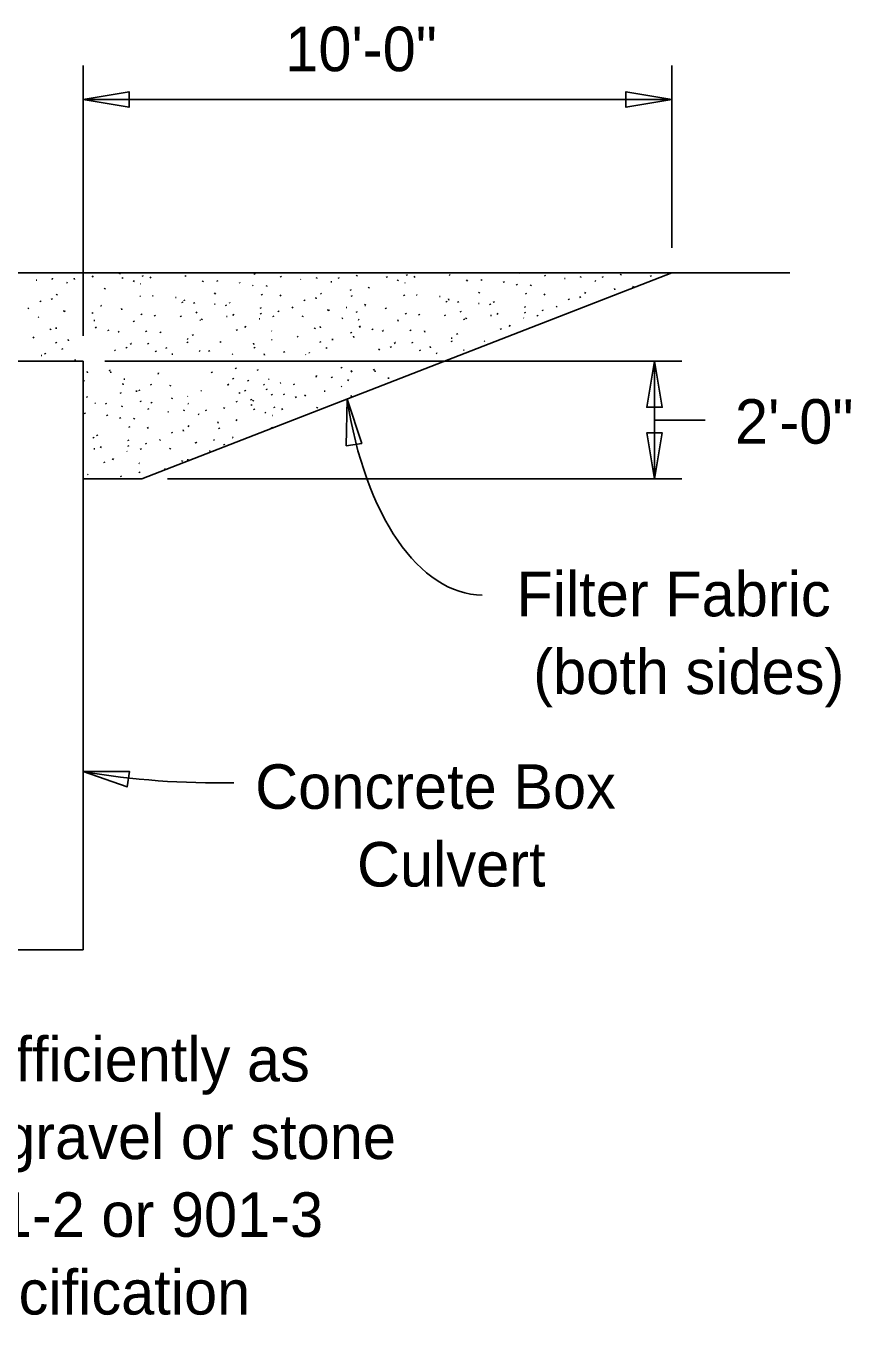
# Model space of a CAD drawing. Extents: x 1.4 to 54.1, y -0.5 to 22.6.
# Drawn here: x 28.703 to 31.505, y 6.775 to 11.198 of the extents above; entities that cross this region are included whole.
import ezdxf

# ---------------------------------------------------------------- set-up
doc = ezdxf.new("R2010")
doc.units = 0
for name, color, linetype in [('AdhocPoint_dp', 7, 'Continuous'), ('Border', 7, 'Continuous'), ('Leader', 7, 'Continuous'), ('PlotBorder_dp', 7, 'Continuous'), ('WallConc', 7, 'Continuous')]:
    doc.layers.add(name, color=color, linetype=linetype)

msp = doc.modelspace()

# ---------------------------------------------------------------- linework, layer by layer
at = {"layer": 'Border'}
for p, q in [((29.0233, 10.3597), (29.0208, 10.3559)), ((29.1005, 10.348), (29.0985, 10.3514)), ((29.2463, 10.3512), (29.2437, 10.3474)), ((29.4801, 10.3578), (29.4782, 10.3545)), ((29.8279, 10.3526), (29.8253, 10.3486)), ((29.9184, 10.3597), (29.9179, 10.3589)), ((29.9976, 10.351), (29.9956, 10.3543)), ((30.1433, 10.3542), (30.1407, 10.3504)), ((30.3766, 10.3597), (30.3753, 10.3575)), ((30.4667, 10.3484), (30.4648, 10.3516)), ((30.7249, 10.3556), (30.7223, 10.3516)), ((30.8263, 10.3472), (30.8244, 10.3505)), ((28.7399, 10.3352), (28.738, 10.3346)), ((28.7935, 10.3417), (28.7922, 10.3378)), ((28.8445, 10.326), (28.8412, 10.3267)), ((28.8681, 10.3378), (28.8668, 10.3417)), ((28.9308, 10.3496), (28.9282, 10.3456)), ((28.972, 10.3084), (28.9694, 10.3045)), ((29.0322, 10.3412), (29.0302, 10.3445)), ((29.0705, 10.3337), (29.0678, 10.3298)), ((29.0934, 10.3225), (29.0923, 10.3228)), ((29.1267, 10.3415), (29.1248, 10.346)), ((29.3051, 10.333), (29.3025, 10.329)), ((29.354, 10.3309), (29.3521, 10.3343)), ((29.4298, 10.3245), (29.4279, 10.3277)), ((29.4742, 10.3153), (29.4723, 10.3185)), ((29.5213, 10.3166), (29.5194, 10.3133)), ((29.5697, 10.3454), (29.5677, 10.3486)), ((29.6369, 10.3382), (29.635, 10.3376)), ((29.6906, 10.3447), (29.6892, 10.3408)), ((29.7416, 10.329), (29.7383, 10.3297)), ((29.7651, 10.3408), (29.7639, 10.3447)), ((29.869, 10.3114), (29.8664, 10.3074)), ((29.9292, 10.3442), (29.9273, 10.3475)), ((29.9675, 10.3367), (29.9649, 10.3328)), ((29.9905, 10.3255), (29.9894, 10.3258)), ((30.0238, 10.3444), (30.0218, 10.349)), ((30.2021, 10.336), (30.1995, 10.332)), ((30.2511, 10.3339), (30.2491, 10.3373)), ((30.3269, 10.3275), (30.3249, 10.3307)), ((30.3712, 10.3183), (30.3694, 10.3215)), ((30.4184, 10.3196), (30.4164, 10.3163)), ((30.534, 10.3412), (30.5321, 10.3405)), ((30.5876, 10.3477), (30.5863, 10.3438)), ((30.6386, 10.332), (30.6353, 10.3326)), ((30.6622, 10.3437), (30.6609, 10.3477)), ((30.7034, 10.3026), (30.7021, 10.3066)), ((30.7661, 10.3144), (30.7635, 10.3104)), ((28.7531, 10.262), (28.7511, 10.2652)), ((28.7916, 10.2692), (28.7903, 10.2731)), ((28.8092, 10.2881), (28.8066, 10.2842)), ((29.0917, 10.2791), (29.0897, 10.2823)), ((29.1346, 10.2814), (29.1326, 10.282)), ((29.2129, 10.2761), (29.2104, 10.2762)), ((29.2418, 10.2644), (29.2404, 10.2683)), ((29.3462, 10.2918), (29.3436, 10.2879)), ((29.505, 10.2845), (29.503, 10.2878)), ((29.505, 10.2845), (29.503, 10.2878)), ((29.5684, 10.2813), (29.5658, 10.2853)), ((29.6502, 10.2649), (29.6481, 10.2682)), ((29.6886, 10.2722), (29.6873, 10.2761)), ((29.7063, 10.2911), (29.7037, 10.2872)), ((29.8063, 10.2996), (29.805, 10.3036)), ((29.8102, 10.2801), (29.8083, 10.2833)), ((29.9888, 10.282), (29.9868, 10.2853)), ((30.0316, 10.2844), (30.0296, 10.285)), ((30.11, 10.2791), (30.1074, 10.2792)), ((30.1322, 10.2608), (30.1302, 10.2641)), ((30.1388, 10.2673), (30.1375, 10.2713)), ((30.1721, 10.2588), (30.1701, 10.2621)), ((30.2432, 10.2948), (30.2406, 10.2909)), ((30.2929, 10.2595), (30.291, 10.2628)), ((30.2929, 10.2595), (30.291, 10.2628)), ((30.402, 10.2875), (30.4001, 10.2908)), ((30.402, 10.2875), (30.4001, 10.2908)), ((30.4654, 10.2843), (30.4628, 10.2883)), ((30.5472, 10.2679), (30.5452, 10.2712)), ((30.5857, 10.2752), (30.5844, 10.2791)), ((30.6033, 10.2941), (30.6007, 10.2902)), ((30.7059, 10.2855), (30.7054, 10.2863)), ((28.7124, 10.2372), (28.7099, 10.2411)), ((28.8327, 10.228), (28.8314, 10.2319)), ((28.8353, 10.228), (28.8334, 10.2312)), ((28.93, 10.2221), (28.9282, 10.2254)), ((28.9596, 10.2503), (28.9569, 10.2477)), ((28.9589, 10.2457), (28.957, 10.2464)), ((29.0289, 10.2345), (29.0276, 10.2384)), ((29.0967, 10.217), (29.0947, 10.2203)), ((29.2352, 10.2578), (29.2332, 10.2611)), ((29.275, 10.2559), (29.2731, 10.2591)), ((29.2829, 10.2232), (29.2815, 10.2272)), ((29.3456, 10.2532), (29.3429, 10.2533)), ((29.3835, 10.248), (29.3815, 10.2512)), ((29.3958, 10.2565), (29.394, 10.2598)), ((29.3958, 10.2565), (29.394, 10.2598)), ((29.409, 10.2199), (29.4057, 10.2154)), ((29.5011, 10.2389), (29.4998, 10.2428)), ((29.5017, 10.2199), (29.4998, 10.2232)), ((29.5618, 10.2278), (29.5598, 10.231)), ((29.6095, 10.2402), (29.607, 10.2441)), ((29.7298, 10.231), (29.7285, 10.2349)), ((29.7324, 10.231), (29.7304, 10.2342)), ((29.7932, 10.2421), (29.7899, 10.2428)), ((29.8271, 10.2251), (29.8252, 10.2283)), ((29.8566, 10.2533), (29.854, 10.2506)), ((29.856, 10.2487), (29.854, 10.2493)), ((29.9259, 10.2375), (29.9246, 10.2414)), ((29.9937, 10.22), (29.9917, 10.2233)), ((30.039, 10.2161), (30.037, 10.2194)), ((30.1799, 10.2262), (30.1786, 10.2302)), ((30.2426, 10.2562), (30.24, 10.2562)), ((30.2805, 10.251), (30.2785, 10.2542)), ((30.306, 10.2229), (30.3027, 10.2183)), ((30.3981, 10.2419), (30.3968, 10.2458)), ((30.3987, 10.2229), (30.3968, 10.2262)), ((30.4588, 10.2307), (30.4569, 10.234)), ((30.5066, 10.2432), (30.504, 10.2471)), ((28.7465, 10.211), (28.7446, 10.2078)), ((28.8059, 10.1699), (28.8054, 10.1744)), ((28.9373, 10.1979), (28.9341, 10.1985)), ((28.9412, 10.1718), (28.9393, 10.1764)), ((29.0701, 10.1934), (29.0688, 10.1973)), ((29.1419, 10.2132), (29.1399, 10.2164)), ((29.2299, 10.2108), (29.228, 10.214)), ((29.2299, 10.2108), (29.228, 10.214)), ((29.2953, 10.1977), (29.2933, 10.2009)), ((29.3018, 10.2043), (29.2992, 10.2003)), ((29.3867, 10.2121), (29.3841, 10.2121)), ((29.4501, 10.1788), (29.4469, 10.1742)), ((29.4972, 10.2035), (29.4952, 10.2042)), ((29.5442, 10.2102), (29.5422, 10.2134)), ((29.5442, 10.2102), (29.5422, 10.2134)), ((29.6435, 10.214), (29.6417, 10.2107)), ((29.703, 10.1728), (29.7024, 10.1774)), ((29.7788, 10.2055), (29.7762, 10.2054)), ((29.8343, 10.2009), (29.8311, 10.2015)), ((29.8383, 10.1748), (29.8363, 10.1794)), ((29.9671, 10.1963), (29.9658, 10.2002)), ((30.127, 10.2138), (30.125, 10.217)), ((30.127, 10.2138), (30.125, 10.217)), ((30.1923, 10.2007), (30.1903, 10.2039)), ((30.1989, 10.2073), (30.1963, 10.2033)), ((30.2837, 10.2151), (30.2811, 10.2151)), ((30.3472, 10.1817), (30.3439, 10.1772)), ((30.3942, 10.2065), (30.3923, 10.2072)), ((30.4412, 10.2131), (30.4392, 10.2164)), ((30.4412, 10.2131), (30.4392, 10.2164)), ((28.7301, 10.1424), (28.7276, 10.1385)), ((28.7877, 10.1698), (28.7857, 10.1666)), ((28.8471, 10.1287), (28.8465, 10.1333)), ((28.9838, 10.1632), (28.9818, 10.1665)), ((29.0184, 10.16), (29.0158, 10.1587)), ((29.0198, 10.1614), (29.019, 10.1609)), ((29.1126, 10.16), (29.1106, 10.1633)), ((29.1606, 10.156), (29.1593, 10.1599)), ((29.2535, 10.135), (29.2502, 10.1357)), ((29.2711, 10.1474), (29.2691, 10.1506)), ((29.4201, 10.1644), (29.4181, 10.1677)), ((29.5383, 10.1624), (29.5364, 10.1631)), ((29.5397, 10.131), (29.5371, 10.1336)), ((29.6272, 10.1454), (29.6246, 10.1415)), ((29.6847, 10.1728), (29.6828, 10.1696)), ((29.7442, 10.1317), (29.7435, 10.1362)), ((29.8082, 10.1552), (29.8062, 10.1584)), ((29.8162, 10.1408), (29.8148, 10.1447)), ((29.8808, 10.1662), (29.8789, 10.1695)), ((29.9155, 10.163), (29.9129, 10.1616)), ((29.9168, 10.1644), (29.916, 10.1639)), ((30.0096, 10.163), (30.0076, 10.1662)), ((30.0576, 10.159), (30.0563, 10.1629)), ((30.1505, 10.138), (30.1472, 10.1386)), ((30.1498, 10.1255), (30.1479, 10.1289)), ((30.1682, 10.1504), (30.1662, 10.1536)), ((30.2616, 10.1262), (30.2596, 10.1295)), ((30.3172, 10.1674), (30.3151, 10.1707)), ((28.7693, 10.0836), (28.7674, 10.0869)), ((28.8066, 10.1209), (28.8046, 10.1241)), ((28.8275, 10.0999), (28.8256, 10.1032)), ((29.0067, 10.0985), (29.004, 10.0946)), ((29.0458, 10.1037), (29.0438, 10.107)), ((29.0596, 10.1188), (29.0569, 10.1175)), ((29.061, 10.1202), (29.0601, 10.1198)), ((29.1191, 10.1182), (29.1171, 10.1215)), ((29.1452, 10.0921), (29.1433, 10.0954)), ((29.1804, 10.1025), (29.179, 10.1064)), ((29.2528, 10.1225), (29.2508, 10.1259)), ((29.2946, 10.0939), (29.2914, 10.0945)), ((29.326, 10.0926), (29.324, 10.0958)), ((29.3646, 10.1232), (29.3625, 10.1265)), ((29.4057, 10.0821), (29.4037, 10.0853)), ((29.4769, 10.1167), (29.4756, 10.1206)), ((29.4802, 10.1043), (29.4782, 10.1075)), ((29.5129, 10.0807), (29.5116, 10.0846)), ((29.5809, 10.0899), (29.5783, 10.0925)), ((29.6664, 10.0866), (29.6645, 10.0899)), ((29.7037, 10.1239), (29.7017, 10.1271)), ((29.7246, 10.1029), (29.7226, 10.1062)), ((29.9037, 10.1015), (29.901, 10.0976)), ((29.9429, 10.1067), (29.9409, 10.11)), ((29.9566, 10.1218), (29.954, 10.1205)), ((29.958, 10.1232), (29.9572, 10.1228)), ((30.0161, 10.1212), (30.0142, 10.1245)), ((30.0422, 10.0951), (30.0403, 10.0984)), ((30.0774, 10.1055), (30.0761, 10.1093)), ((30.0991, 10.0865), (30.0958, 10.0872)), ((30.1916, 10.0968), (30.1884, 10.0975)), ((30.222, 10.0973), (30.2211, 10.0988)), ((28.7569, 10.079), (28.755, 10.0797)), ((28.8714, 10.0613), (28.8695, 10.0659)), ((29.202, 10.0836), (29.1988, 10.0842)), ((29.654, 10.082), (29.6521, 10.0827)), ((28.9126, 10.0201), (28.9106, 10.0248)), ((28.9884, 10.0267), (28.9863, 10.03)), ((28.9884, 10.0267), (28.9863, 10.03)), ((28.9916, 10.0207), (28.9903, 10.0248)), ((29.0393, 9.9993), (29.0354, 9.9993)), ((29.153, 10.0201), (29.1517, 10.0162)), ((29.3349, 10.0208), (29.3329, 10.024)), ((29.4076, 9.999), (29.4057, 10.0023)), ((29.4169, 10.0344), (29.4149, 10.0376)), ((29.4906, 10.0285), (29.4888, 10.0317)), ((29.5286, 9.9971), (29.5266, 10.0003)), ((29.69, 10.0107), (29.6881, 10.0061)), ((29.7429, 10.0036), (29.7411, 10.0068)), ((29.7429, 10.0036), (29.7411, 10.0068)), ((29.7756, 10.0362), (29.7737, 10.0395)), ((29.7985, 9.9977), (29.7959, 9.9936)), ((29.8096, 10.0231), (29.8077, 10.0277)), ((29.8854, 10.0297), (29.8834, 10.033)), ((29.8854, 10.0297), (29.8834, 10.033)), ((29.8886, 10.0237), (29.8873, 10.0277)), ((29.9364, 10.0022), (29.9324, 10.0022)), ((28.9015, 9.9947), (28.8988, 9.9907)), ((29.0256, 9.9502), (29.0236, 9.9535)), ((29.0327, 9.9796), (29.0315, 9.9836)), ((29.0805, 9.9581), (29.0766, 9.9581)), ((29.0889, 9.9587), (29.087, 9.962)), ((29.1281, 9.9783), (29.1269, 9.9823)), ((29.1942, 9.9789), (29.1928, 9.9751)), ((29.2994, 9.9575), (29.2974, 9.9607)), ((29.392, 9.9819), (29.388, 9.9779)), ((29.4293, 9.954), (29.4267, 9.95)), ((29.4488, 9.9578), (29.4469, 9.9611)), ((29.4587, 9.9925), (29.4567, 9.9958)), ((29.5135, 9.982), (29.5096, 9.9781)), ((29.5214, 9.9624), (29.5194, 9.9658)), ((29.5684, 9.986), (29.5665, 9.9853)), ((29.6141, 9.9794), (29.6123, 9.9827)), ((29.7194, 9.9578), (29.7155, 9.9578)), ((29.7757, 9.9722), (29.7736, 9.9755)), ((29.7757, 9.9722), (29.7736, 9.9755)), ((29.7757, 9.9722), (29.7736, 9.9755)), ((29.9295, 9.9835), (29.9285, 9.9866)), ((28.9113, 9.9366), (28.9093, 9.9398)), ((28.9387, 9.9156), (28.9367, 9.9189)), ((28.9759, 9.9136), (28.9739, 9.9169)), ((29.0301, 9.9078), (29.0282, 9.9045)), ((29.0935, 9.9215), (29.0915, 9.9248)), ((29.1301, 9.9176), (29.1281, 9.9208)), ((29.1993, 9.9359), (29.1981, 9.9319)), ((29.253, 9.9398), (29.2511, 9.9405)), ((29.2555, 9.915), (29.2523, 9.9156)), ((29.4194, 9.9206), (29.4181, 9.9245)), ((29.4685, 9.9278), (29.4665, 9.9311)), ((29.4704, 9.9128), (29.4678, 9.9088)), ((29.4763, 9.9278), (29.4737, 9.9239)), ((29.5391, 9.9448), (29.5371, 9.9481)), ((29.5391, 9.9448), (29.5371, 9.9481)), ((29.5802, 9.9455), (29.5783, 9.9487)), ((29.6202, 9.9356), (29.6189, 9.9395)), ((29.6521, 9.9454), (29.6496, 9.9415)), ((29.7575, 9.9167), (29.7567, 9.9166)), ((29.8083, 9.9396), (29.8063, 9.9428)), ((28.904, 9.8809), (28.902, 9.8842)), ((28.9798, 9.8745), (28.9778, 9.8777)), ((29.0242, 9.8653), (29.0223, 9.8685)), ((29.0713, 9.8666), (29.0694, 9.8633)), ((29.1197, 9.8954), (29.1177, 9.8986)), ((29.1869, 9.8882), (29.185, 9.8875)), ((29.2405, 9.8947), (29.2392, 9.8908)), ((29.2915, 9.879), (29.2883, 9.8796)), ((29.3151, 9.8907), (29.3139, 9.8947)), ((29.3778, 9.9026), (29.3752, 9.8986)), ((29.4792, 9.8942), (29.4773, 9.8975)), ((29.5175, 9.8867), (29.5148, 9.8828)), ((29.5405, 9.8755), (29.5393, 9.8758)), ((29.5475, 9.901), (29.5456, 9.9043)), ((29.5738, 9.8944), (29.5718, 9.899)), ((29.6933, 9.9042), (29.6907, 9.9004)), ((29.0549, 9.8345), (29.053, 9.8378)), ((29.0549, 9.8345), (29.053, 9.8378)), ((29.1184, 9.8313), (29.1158, 9.8353)), ((29.2386, 9.8222), (29.2373, 9.8261)), ((29.2562, 9.8411), (29.2536, 9.8372)), ((29.3563, 9.8496), (29.355, 9.8536)), ((29.3602, 9.83), (29.3583, 9.8333)), ((29.419, 9.8614), (29.4164, 9.8574)), ((29.5388, 9.832), (29.5367, 9.8353)), ((28.9334, 9.798), (28.9315, 9.8012)), ((28.9458, 9.8065), (28.944, 9.8097)), ((28.9458, 9.8065), (28.944, 9.8097)), ((29.051, 9.7889), (29.0497, 9.7928)), ((29.1117, 9.7777), (29.1098, 9.781)), ((29.1595, 9.7902), (29.1569, 9.7941)), ((29.2001, 9.8149), (29.1981, 9.8182)), ((29.2798, 9.781), (29.2785, 9.7849)), ((29.2824, 9.781), (29.2804, 9.7842)), ((29.3431, 9.7921), (29.3399, 9.7927)), ((29.3771, 9.7751), (29.3752, 9.7783)), ((29.4066, 9.8033), (29.404, 9.8006)), ((29.4059, 9.7986), (29.404, 9.7993)), ((28.9367, 9.7621), (28.9341, 9.7621)), ((28.9589, 9.7699), (28.9557, 9.7653)), ((29.0471, 9.7535), (29.0452, 9.7542)), ((29.0517, 9.7699), (29.0497, 9.7732)), ((29.0941, 9.7601), (29.0922, 9.7634)), ((29.0941, 9.7601), (29.0922, 9.7634)), ((29.1935, 9.764), (29.1916, 9.7607)), ((29.3288, 9.7555), (29.3262, 9.7554)), ((28.9701, 9.7144), (28.9681, 9.7177)), ((29.0001, 9.7287), (28.9969, 9.7242)), ((29.0883, 9.7124), (29.0863, 9.7131)), ((29.1772, 9.6953), (29.1746, 9.6914)), ((29.2347, 9.7228), (29.2328, 9.7196)), ((29.253, 9.7228), (29.2524, 9.7274)), ((28.9145, 9.6732), (28.9125, 9.6765)), ((29.0269, 9.6666), (29.0255, 9.6706)), ((29.0897, 9.681), (29.0871, 9.6836))]:
    msp.add_line(p, q, dxfattribs=at)
at = {"layer": 'Leader'}
msp.add_arc((29.356, 11.3951), 2.768, 260.4513, 271.09, dxfattribs=at)
msp.add_ellipse((30.2607, 10.2042), major_axis=(0.0083, 0.9392), ratio=0.517574, start_param=1.870693, end_param=3.141593, dxfattribs=at)
at = {"layer": 'PlotBorder_dp'}
for p, q in [((28.8968, 10.1458), (28.8968, 11.0644)), ((30.8968, 10.4447), (30.8968, 11.0644)), ((28.8968, 10.9489), (30.8968, 10.9489)), ((28.9712, 10.0597), (30.9309, 10.0597)), ((30.8374, 9.6597), (30.8374, 10.0597)), ((30.8374, 9.8597), (31.0094, 9.8597)), ((29.1833, 9.6597), (30.9309, 9.6597))]:
    msp.add_line(p, q, dxfattribs=at)
for points in [[(28.8968, 10.9489), (29.053, 10.9224), (29.053, 10.9753)], [(30.8968, 10.9489), (30.7406, 10.9753), (30.7406, 10.9224)], [(30.8374, 10.0597), (30.811, 9.9036), (30.8639, 9.9036)], [(29.7938, 9.9308), (29.791, 9.7724), (29.8433, 9.7803)], [(30.8374, 9.6597), (30.8639, 9.8159), (30.811, 9.8159)], [(28.8968, 8.6654), (29.0465, 8.6134), (29.0552, 8.6656)]]:
    msp.add_lwpolyline(points, close=True, dxfattribs=at)
at = {"layer": 'WallConc'}
for p, q in [((31.2968, 10.3597), (23.6968, 10.3597)), ((29.0968, 9.6597), (30.8968, 10.3597)), ((28.8968, 10.0597), (26.0968, 10.0597)), ((28.8968, 8.0597), (28.8968, 10.0597)), ((28.8968, 9.6597), (29.0968, 9.6597)), ((28.8968, 8.0597), (26.0968, 8.0597))]:
    msp.add_line(p, q, dxfattribs=at)

# ---------------------------------------------------------------- texts
at = {"layer": 'AdhocPoint_dp'}
for s, p in [('10\'-0"', (29.5836, 11.045)), ('Filter Fabric', (30.3686, 9.1931)), ('(both sides)', (30.4257, 8.9291)), ('Concrete Box', (29.4814, 8.5391)), ('Culvert', (29.8273, 8.2751)), ('Place coarse aggregate in 6 inch lifts and compact sufficiently as', (23.8791, 7.613)), ('to be firm and unyielding.  Provide coarse aggregate gravel or stone', (23.8791, 7.349)), ('meeting the requirements of Specification Section 901-2 or 901-3', (23.8791, 7.085)), ('respectively.  Meet the gradation requirements of Specification', (23.8791, 6.821))]:
    msp.add_text(s, height=0.1512, dxfattribs=at).set_placement(p)
msp.add_text('2\'-0"', height=0.1512, rotation=360, dxfattribs=at).set_placement((31.1107, 9.7796))

doc.saveas('drawing.dxf')
